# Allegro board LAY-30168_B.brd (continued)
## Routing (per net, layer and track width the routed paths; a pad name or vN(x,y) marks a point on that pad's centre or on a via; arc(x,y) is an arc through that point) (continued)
P3V3_SDA: length 106.9
  TOP w0.203: U44.1 144.91,88.9 C270.1
  TOP w0.279: 95.26,91.95 95.26,92.58 95.9,93.22 R418.2
  TOP w0.305: 95.26,91.95 U48.1 95.26,89.35 U49.1 v2(109.86,89.35) ; v2(111.51,95.38) 112.61,95.38 113.17,95.94 U46.1 113.98,96.46 R413.1 116.08,95.89 116.64,96.45 U45.3 ; U40.5 v2(143.2,83.44) 143.2,84.13 R378.1 ; U38.C5 v2(128.41,73.37) ; U38.D2 v2(129.21,70.97) U38.D1 v2(129.21,70.17) ; v2(125.09,80.51) R213.1 121.66,85.35 119.38,87.63 118.11,87.63 J34.1 116.33,86.74 115.32,85.72 114.43,85.72 114.43,86.11 v2(114.05,86.49) ; R388.2 138.18,74.55 v2(137.92,74.8) 137.92,77.22 138.94,78.23 ; U38.B2 v2(127.61,71.77) ; R215.1 127.25,66.17 126.11,67.31 126.11,68.33 ; v2(145.03,90.55) 145.03,91.44 144.65,91.82 142.62,91.82 R402.2 ; R394.1 146.42,89.16 v2(146.43,89.15) C270.1 145.54,86.74 v2(145.29,86.49) ; U38.F10 v2(130.81,78.17) ; U38.K5 v2(134.01,74.17) ; v2(122.17,76.07) R382.1 R381.1 R390.2
  TOP w0.381: v2(122.43,72.01) R383.1 123.07,72.76 R423.1 ; R381.1 v2(122.17,75.06)
  BOTTOM w0.127: 127.89,71.37 128.91,71.37
  BOTTOM w0.305: v2(134.01,74.17) 134.14,74.04 137.16,74.04 v2(137.92,74.8) ; 129.91,70.87 129.91,70.6 129.48,70.17 v2(129.21,70.17) ; 129.91,70.87 129.81,70.97 v2(129.21,70.97) ; 129.91,70.87 C265.1 ; v2(145.03,90.55) v2(146.43,89.15) ; 130.81,77.34 v2(130.81,78.17) ; C262.1 127.38,72 v2(127.61,71.77) ; v2(114.05,86.49) 112.72,86.49 v2(109.86,89.35) 109.86,93.73 v2(111.51,95.38) ; v2(128.41,73.37) 128.14,73.63 C266.1 ; v2(143.2,83.44) 143.2,84.39 v2(145.29,86.49)
  BOTTOM w0.381: v2(122.43,72.01) 122.43,74.8 v2(122.17,75.06)
  vias: v2(123.83,68.71) v2(124.84,68.71) v2(125.73,68.71) v2(139.06,80.26) v2(139.06,79.38) v2(139.95,80.26) v2(139.95,79.38) v2(139.95,78.36)
P5V0_SDA_USB_CONN_VBUS: length 17.9
  TOP w0.381: v2(144.78,71.12) 145.25,71.59 J41.1 ; L23.1 146.75,77.54 v2(146.43,77.22) 143.99,74.77 v2(141.25,74.77) ; v2(141.22,73.5) U39.4
  BOTTOM w0.381: v2(146.43,77.22) 144.4,75.18 144.4,73.66 144.78,73.28 v2(144.78,71.12) ; v2(141.25,74.77) 141.22,74.74 v2(141.22,73.5)
P5V_SDA: length 8.1
  TOP w0.254: U31.C1 U31.B1 U31.B2
  TOP w0.305: R212.1 125.48,63.12 125.98,62.61 130.81,62.61
  TOP w0.381: R379.1 v2(139.19,69.72)
  vias: v2(137.67,66.93) v2(138.56,66.93) v2(139.45,66.93) v2(139.7,75.69) v2(140.59,75.69) v2(141.48,75.69)
P5V_SDA_S:
  vias: v2(136.02,65.02) v2(136.02,64.14) v2(136.78,65.02) v2(136.78,64.14)
VDD_COIN_3V: length 5.7
  TOP w0.305: J6.2 88.48,39.37 D5.A 88.48,38.31 88,37.84 R16.1
VDD_HIGH_IN_3V3: length 59.9
  TOP w0.381: v2(83.19,31.11) 83.19,40.51 82.42,41.27 76.58,41.27 74.93,42.93 R14.1 75.82,44.96 76.33,44.45 J4.1 ; v2(65.41,29.21) 65.41,24.77 57.65,17.01 R311.2 R310.2
  BOTTOM w0.381: v2(65.41,29.21) 66.17,28.45 80.52,28.45 v2(83.19,31.11)
VDD_HIGH_IN_MCU: length 20.6
  TOP w0.203: U1.P12 61.35,50.82 61.73,50.43 62.5,50.43 63.02,49.91 63.37,49.91
  TOP w0.305: J4.2 76.48,46.99 75.97,46.48 R14.2 74.12,46.48 v2(73.79,46.82) ; 63.37,49.91 65.15,49.91 65.33,49.73 66.37,49.73 67.43,50.79 C15.1 v2(68.45,50.79)
  BOTTOM w0.305: v2(68.45,50.79) C16.1 72.14,50.79 73.79,49.15 v2(73.79,46.82)
VDD_SNVS_3V3: length 78.5
  TOP w0.305: v2(81.92,20.95) 81.92,31.53 D4.A ; U5.4 C59.1 42.8,21.21 44.32,19.68 44.32,18.29 47.24,15.37 47.24,9.4 48.18,8.46 58.88,8.46 v2(59.44,9.02) 59.69,9.27 59.69,14.1 R354.2 58.68,14.23 58.55,14.1
  TOP w0.381: 58.55,14.1 R34.2
  BOTTOM w0.305: v2(81.92,20.95) 78.36,17.4 78.36,15.49 71.58,8.71 59.74,8.71 v2(59.44,9.02)
VDD_SNVS_IN: length 31.8
  TOP w0.102: 59.23,50.24 59.05,50.42 59.05,51.98 U1.M9
  TOP w0.254: v2(59.39,47.45) 59.27,47.56 59.27,50.2 59.23,50.24
  TOP w0.305: v2(67.69,40.13) 73.66,40.13 75.32,38.47 C23.1 77.97,38.47 78.36,38.86 R15.2 80.77,38.86 J5.2
  BOTTOM w0.305: v2(67.69,40.13) 65.48,40.13 59.81,45.8 R21.1 59.81,47.02 v2(59.39,47.45)
VDD_SOC_IN: length 23.5
  TOP w0.254: U1.H9 v1(59.07,54.59) U1.J9 v1(59.72,54.6) U1.H9 ; U1.H9 59.72,55.24 U1.G9 59.54,55.72 59.54,56.07 U1.F9 59.39,56.22 v1(59.07,56.54) U1.F8 U1.F7 v1(57.77,56.54) U1.F6 v1(57.12,55.89) U1.G6 v1(57.12,55.24) U1.H6 ; U1.J5 v1(56.47,53.95)
  INT1 w0.102: 58.09,52.32 58.09,51.24 ; 58.09,52.32 58.09,52.97 ; 58.09,52.32 58.1,52.32 60.04,52.32 60.04,52.32 ; v1(56.47,53.95) 56.49,53.95 56.79,54.25 56.79,54.92 v1(57.12,55.24) ; 58.09,52.97 60.04,52.97 60.04,52.98 ; 58.09,52.97 58.09,53.63 ; 60.04,53.66 60.01,53.62 58.1,53.62 58.09,53.63 ; 60.04,53.66 60.04,52.98 ; 60.04,53.66 60.04,54.25 ; 60.04,52.98 60.04,52.32 ; 60.04,52.32 60.04,51.62 ; 58.09,54.26 58.09,54.92 ; 58.09,54.26 58.1,54.27 58.76,54.27 ; 58.09,54.26 58.09,53.63
  BOTTOM w0.305: C11.1 58.11,56.89 v1(57.77,56.54)
  vias: v2(49.53,44.07) v2(49.91,44.7) v2(49.91,43.56)
VDD_USB_3V: length 7.5
  TOP w0.254: v1(58.42,53.94) 58.74,53.62 U1.K8
  BOTTOM w0.127: 59.13,53.34 58.85,53.34 58.42,53.77 v1(58.42,53.94)
  BOTTOM w0.152: 59.13,53.34 59.31,53.16 59.31,51.31 59.56,51.05
  BOTTOM w0.305: 59.56,51.05 59.82,50.8 C83.1 61.62,48.49 C82.1
VDDA_ADC_3P3_MCU: length 23.9
  TOP w0.203: U1.N14 62.73,51.59 69.01,51.59 69.22,51.38 C7.1
  TOP w0.305: C7.1 C6.1 71.38,50.79 73.77,48.41 78.34,48.41 80.26,46.48 R12.2 82.42,46.48 82.93,46.99 J3.2
VDDA_ADC_3V3: length 5.2
  TOP w0.305: R12.1 C57.1 81.02,43.55 R44.2
  TOP w0.381: R12.1 82.3,44.96 82.8,44.45 J3.1
AUD_INT: length 111.2
  TOP w0.127: R96.1 v2(121.41,21.6) 120.41,21.6 119.63,20.83 101.85,20.83 100.08,22.61 100.08,31.75 94.11,37.72 94.11,44.45 92.46,46.1 v2(92.46,46.61) ; U1.H13 62.17,54.92 62.51,54.59 63.14,54.59 63.58,54.15 75.18,54.15 77.17,52.16 79.61,52.16 80.16,52.7 88.81,52.7 89.57,53.47 R287.2 v2(90.05,52.71) ; R222.2 v2(133.99,14.99) R275.1
  BOTTOM w0.127: v2(133.99,14.99) 133.05,14.99 132.16,15.88 129.92,15.88 129.71,15.66 123.32,15.66 121.92,17.06 121.92,18.16 122.53,18.77 122.53,21.11 122.03,21.6 v2(121.41,21.6) ; v2(90.05,52.71) 92.46,50.3 v2(92.46,46.61)
BACKLIGHT_CTL: length 90
  TOP w0.127: U8.4 v2(94.36,67.63) 93.54,68.45 R314.1 ; v2(96.14,31.11) 90.3,31.11 86.36,27.18 R344.1 ; U1.B14 63.53,58.82 64.85,60.15 84.4,60.15 v2(85.85,61.59) 86.33,62.08 87.48,62.08 87.83,61.72 87.83,61.16 87.5,60.83 87.5,58.8 v2(87.88,58.42)
  BOTTOM w0.127: v2(94.36,67.63) 94.04,67.63 92.2,65.79 92.2,64.52 89.92,62.23 86.49,62.23 v2(85.85,61.59) ; v2(96.14,31.11) 98.17,33.15 98.17,48.73 89.12,57.78 88.14,57.78 87.88,58.04 v2(87.88,58.42)
BL+: length 5.6
  TOP w0.254: R63.2 v2(91.57,67.56)
  BOTTOM w0.254: J8.A2 94.15,69.55 94.23,69.47 94.23,68.96 92.84,67.56 v2(91.57,67.56)
BL-:
  vias: v2(96.27,70.99) v2(96.27,70.1)
BOOT0_LED: length 4.4
  TOP w0.127: U38.K2 135.63,71.37 R392.1 R388.1
BOOT1: length 3.3
  TOP w0.127: U38.K1 135.85,70.57 R389.1
BOOT2: length 5.1
  TOP w0.127: U38.C6 128.41,74.17 124.08,74.17 R390.1
BOOT3: length 4.8
  TOP w0.127: U38.B10 126.28,79.5 R391.1
BOOT_FLASH: length 5.8
  TOP w0.127: J42.2 128.81,79.6 U38.C10
CAN1_H: length 16
  TOP w0.107: R87.2 FL1.1 65.18,12.46 65.48,12.16 R88.1 65.48,9.4 C101.2 65.48,9.4 D11.2 66.2,8.01 66.3,7.9 66.3,7.23 66.11,7.04 63.99,7.04 63.49,6.54 63.49,5.08 61.82,3.4 J11.1
CAN1_L: length 16.3
  TOP w0.107: J11.3 65.43,3.4 63.75,5.08 63.75,6.43 64.1,6.78 64.69,6.78 64.8,6.67 64.8,6.51 64.9,6.4 65.12,6.4 65.22,6.51 65.22,6.67 65.33,6.78 66.21,6.78 66.56,7.13 66.56,7.9 66.67,8.01 D11.1 67.38,9.4 C103.1 67.38,9.4 R89.2 67.38,12.16 67.68,12.46 FL1.2 R91.2
CAN2_RX: length 45.3
  TOP w0.127: v2(71.75,35.43) 72.78,34.4 U12.4 ; U1.L10 v1(60.37,52.65)
  BOTTOM w0.102: 64.14,50.16 62.69,50.16 61.18,51.67 60.89,51.67 60.7,51.86 60.7,52.15 60.37,52.48 v1(60.37,52.65)
  BOTTOM w0.127: v2(71.75,35.43) 74.3,37.97 74.3,49.4 72.26,51.44 68.33,51.44 67.06,50.16 64.14,50.16
CAN2_TX: length 49.6
  TOP w0.127: U1.H14 63.68,54.92 63.83,55.07 66.68,55.07 66.9,55.28 72.22,55.28 72.57,54.94 75.06,54.94 v2(77.42,52.58) ; U12.1 76.59,31.48 v2(72.64,35.43)
  BOTTOM w0.127: v2(77.42,52.58) 74.8,49.96 74.8,37.59 v2(72.64,35.43)
CAN_STBY: length 156
  TOP w0.127: SW7.3 87.98,82.07 R260.2 88.78,81.78 89.03,81.53 89.03,80.77 89.41,80.39 104.31,80.39 106.17,78.53 106.17,73.91 106.97,73.11 106.97,57.84 103.83,54.7 87.46,54.7 86.36,53.59 79.79,53.59 v2(79.63,53.44) 79.14,52.95 78.4,52.95 75.52,55.83 72.95,55.83 72.72,56.06 66.4,56.06 66.17,55.83 63.7,55.83 63.44,55.57 U1.G14 ; v2(60.2,37.34) 62.48,37.34 65.02,34.8 66.04,34.8 68.58,32.26 v2(68.58,31.75) 72.01,28.32 72.01,20.95 72.9,20.07 75.32,20.07 v2(76.59,18.8)
  BOTTOM w0.127: v2(60.2,37.34) 59.94,37.34 58.67,38.61 58.67,40.26 57.15,41.78 R169.1 ; v2(68.58,31.75) 73.01,31.75 78.99,37.73 78.99,49.91 78.61,50.29 78.61,51.69 79.63,52.7 v2(79.63,53.44) ; R92.1 v2(76.59,18.8)
CAN_VIO_3V3: length 6
  TOP w0.305: U12.5 v2(72.78,16)
  BOTTOM w0.305: C100.1 v2(72.78,16) R86.1 73.67,16.77 74.42,17.52 R90.1
CSI_1V8: length 3.6
  TOP w0.305: v2(133.35,5.84) 133.96,6.46 J35.15
  BOTTOM w0.305: L20.2 133.35,5.21 v2(133.35,5.84)
  BOTTOM w0.381: C247.1 v2(133.35,5.84)
CSI_D2: length 20.1
  TOP w0.127: v2(124.08,16.26) 124.59,15.75 124.59,12.45 127,10.03 127.76,10.03 129.47,8.33 J35.6
  BOTTOM w0.127: R229.1 123.3,24.14 124.08,23.37 v2(124.08,16.26)
CSI_D3: length 19
  TOP w0.127: J35.4 128.47,8.19 127.38,9.27 126.62,9.27 123.32,12.57 v2(123.32,17.14)
  BOTTOM w0.127: R228.1 123.44,23.11 123.7,22.86 123.7,17.53 v2(123.32,17.14)
CSI_D4: length 17.6
  TOP w0.127: J35.3 127.96,8.18 127.38,8.76 126.62,8.76 122.43,12.95 v2(122.43,17.14)
  BOTTOM w0.127: v2(122.43,17.14) 122.93,17.65 R227.1
CSI_D5: length 17.1
  TOP w0.127: J35.5 128.96,8.2 127.51,9.65 126.75,9.65 124.08,12.32 v2(124.08,15.24)
  BOTTOM w0.127: R226.1 122.04,19.17 121.54,18.67 121.54,16.9 123.2,15.24 v2(124.08,15.24)
CSI_D6: length 4.4
  TOP w0.127: J35.7 129.96,8.34 128.4,9.91 128.4,10.41 128.26,10.55 R225.1
CSI_D7: length 3.4
  TOP w0.127: R224.1 130.18,9.78 130.96,8.99 J35.9
CSI_D8: length 27.2
  TOP w0.127: v2(131.44,14.99) 131.44,10.55 131.96,10.03 J35.11
  BOTTOM w0.127: v2(131.44,14.99) 130.94,15.49 130.3,15.49 129.57,14.76 123.25,14.76 119.89,18.12 119.89,20.19 119.76,20.32 R223.1
CSI_D9: length 3.6
  TOP w0.127: R222.1 132.87,9.43 132.87,8.61 132.96,8.52 J35.13
CSI_HSYNC: length 3.5
  TOP w0.127: J35.16 134.47,9.88 135.13,10.55 R221.1
CSI_MCLK: length 3.2
  TOP w0.127: J35.12 132.47,10.3 R218.1
CSI_PIXCLK: length 3.8
  TOP w0.127: J35.8 130.47,8.47 128.91,10.03 R217.1
CSI_PWDN: length 252.2
  TOP w0.127: D17.C v2(137.53,15.24) ; v2(85.47,50.8) 84.96,50.29 84.96,49.63 85.44,49.15 86.36,49.15 87,49.78 v2(91.82,49.78) 103.12,49.78 108.58,55.24 v2(113.67,55.24) 118.24,50.67 118.24,46.86 J38.2 ; U1.L11 v1(61.02,52.65)
  BOTTOM w0.102: 64.82,52.12 61.71,52.12 61.19,52.65 v1(61.02,52.65)
  BOTTOM w0.127: v2(85.47,50.8) 82.8,53.47 81.56,53.47 80.19,54.84 76.3,54.84 74.24,52.78 67.39,52.78 66.73,52.12 64.82,52.12 ; v2(113.67,55.24) 113.67,61.34 87.47,87.53 59.6,87.53 54.37,82.3 34.14,82.3 J22.7 ; v2(91.82,49.78) 91.82,43.4 92.43,42.8 93.34,42.8 95.63,40.51 95.63,35.81 94.61,34.8 94.61,26.92 97.28,24.26 117.86,24.26 118.92,23.19 118.92,18.66 123.13,14.45 136.74,14.45 v2(137.53,15.24)
CSI_VSYNC: length 4.4
  TOP w0.127: J35.18 135.47,8.72 135.76,9.02 136.14,9.02 137.67,10.55 R220.1
DC_5V_IN: length 6.2
  BOTTOM w0.381: v2(14.99,14.22) 16.76,14.22 17.4,14.86 R6.1
DCDC_3V3: length 175.4
  TOP w0.203: C268.1 144.4,87.12 143.66,87.86 U44.8
  TOP w0.254: U1.J10 v1(60.37,53.95) ; C252.1 28.52,36.76 U37.A1 ; U1.F5 v1(57.12,56.54) U1.E6 v1(57.12,57.19) ; U1.E9 U1.F10 v1(60.37,56.54)
  TOP w0.305: U48.8 95.26,95.62 C277.1 ; R57.1 v2(74.93,50.8) ; v2(143.38,85.6) 143.38,86.11 143.89,86.61 C268.1 ; R324.1 93.34,70.99 v2(94.11,71.75) ; v2(55.75,82.29) R284.1 v2(57.28,82.29) ; R179.1 v2(45.47,86.62) ; R293.1 v2(68.95,39.36) ; R245.1 v2(87.98,93.09) ; U46.6 113.17,93.08 C276.1 v2(114.43,92.71) ; R244.1 v2(86.71,93.09) ; v2(118.24,91.95) R411.1 117.47,91.19 C275.1 117.29,91.37 U45.7 ; C220.1 v2(87.38,65.28) ; v2(82.3,51.05) C198.1 ; J35.14 133.47,8.82 v2(133.39,8.9) ; R246.1 v2(89.25,93.09) ; R419.2 v2(110.62,93.22) ; R412.1 129.79,87.88 v2(130.05,87.63) ; R243.1 v2(85.44,93.09) ; R236.1 v2(70.2,93.09) ; R354.1 v2(59.56,16) ; R27.1 v2(27.81,43.18) ; v2(140.34,14.61) 140.21,14.48 R232.1 ; R239.1 v2(77.18,93.09) ; R238.1 v2(72.74,93.09) ; R422.2 v2(92.71,87.12) ; v2(83.06,19.43) 85.72,16.76 R332.1 R349.1 ; R241.1 v2(79.72,93.09) ; D12.A v2(29.84,84.84) ; C199.1 89.03,47.62 v2(88.01,48.64) ; R242.1 v2(80.99,93.09) ; R234.1 v2(138.69,14.47) ; R393.1 v2(125.47,90.94) ; R235.1 v2(68.93,93.09) ; R237.1 v2(71.47,93.09) ; R240.1 v2(78.45,93.09)
  TOP w0.381: R44.1 80.14,42.29 v2(80.39,42.04) ; R219.1 136.4,11.3 v2(137.03,11.94) ; R316.1 v2(97.54,41.66) ; R177.1 v2(39.64,85.85) ; C278.1 95.5,86.01 v2(95.26,86.25) U49.6 ; C252.1 v2(28.84,35.69) ; v2(118.87,24) 119.25,23.62 C196.1 ; C209.1 v2(33.27,88.01) ; C206.1 v2(113.41,83.06) ; R311.1 v2(56.13,16.13) ; R350.1 v2(89.41,27.18) ; R176.1 v2(37.1,85.85) ; v2(24.13,58.93) 24.77,59.56 v2(24.77,67.31) ; C216.1 v2(79.63,77.09) ; C277.1 v2(93.6,96.39) ; C207.1 v2(40.89,88.01) ; R401.1 v2(143.38,85.6) ; v2(128.4,12.06) 128.4,12.7 C203.1 ; R178.1 v2(42.18,85.85) ; R174.1 v2(24.4,85.85) ; C212.1 v2(80.77,55.37) ; C208.1 v2(102.87,78.74) ; C200.1 v2(91.57,24) ; C204.1 v2(132.33,14.99) ; R346.1 v2(87.38,27.18)
  INT1 w0.102: v1(57.12,57.19) 57.3,57.19 57.62,57.52 58.29,57.52 ; v1(57.12,57.19) v1(57.12,56.54) 57.31,56.54 57.63,56.87 58.01,56.87 58.29,57.15 ; v1(57.12,57.19) 57.12,57.37 57.44,57.7 57.44,57.98 57.64,58.17 58.29,58.17 ; 60.69,52.97 60.69,53.62 ; 60.69,52.97 60.69,52.32 ; 60.69,52.97 62,52.97 ; 60.69,53.62 v1(60.37,53.95) 60.69,54.27 ; 60.69,53.62 62,53.62 ; 61.35,51.74 61.35,57.52 ; 61.35,57.52 60.21,57.52 ; 61.35,57.52 61.35,58.97 ; 60.04,58.17 60.04,58.82 61.43,58.82 ; 60.04,58.17 59.1,58.17 ; 60.04,58.17 61.43,58.17 ; 60.04,58.17 60.04,57.63 ; 62,54.92 60.71,54.92 60.69,54.93 ; 60.69,54.27 60.69,54.93 ; 60.69,54.27 62,54.27 ; 60.69,54.93 60.69,56.52 ; 62,56.22 60.75,56.22 ; 59.39,58.82 59.39,57.57 ; 60.69,52.32 60.69,51.63 ; 60.69,52.32 62,52.32 ; 60.69,59.04 60.69,56.91
  BOTTOM w0.254: C72.1 59.92,56.99 v1(60.37,56.54) ; v2(64.9,54.61) R55.1
  BOTTOM w0.305: C221.1 80.01,64.95 v2(80.52,65.46) ; R325.1 83.94,73.54 v2(83.82,73.66)
  BOTTOM w0.381: v2(105.41,51.31) 105.97,50.75 C211.1 ; C219.1 v2(86.26,59.18) ; C210.1 108.84,52.7 v2(108.84,52.96) ; v2(111,43.05) C193.1 ; C201.1 v2(77.09,27.69) ; C202.1 v2(131.95,12.06) ; L19.2 136.77,7.89 R230.1 C249.1 137.36,10.03 v2(137.62,9.78) ; v2(143.38,85.6) 141.99,84.2 133.48,84.2 v2(130.05,87.63) 126.74,90.94 v2(125.47,90.94) 124.46,91.95 v2(118.24,91.95) ; C217.1 100.46,59.31 v2(99.57,58.42) ; C222.1 v2(10.54,55.37) ; C195.1 v2(118.36,19.68) ; v2(137.03,11.94) 136.65,12.32 136.14,12.32 ; C215.1 v2(87.38,81.79) ; C246.1 133.35,8.86 v2(133.39,8.9) ; C214.1 v2(70.1,79.76) ; v2(71.75,17.52) R86.2 ; C213.1 77.09,83.44 76.71,83.06 v2(76.33,83.06) ; v2(120.52,20.45) 120.4,20.57 C194.1 ; C218.1 v2(68.71,66.55) ; R130.1 v2(112.64,41.82) ; R372.1 22.1,56.9 v2(24.13,58.93) ; C197.1 v2(91.49,53.47)
  vias: v2(27.56,67.94) v2(28.57,67.94) v2(33.15,41.88) v2(33.91,41.88) v2(34.67,41.88) v2(46.23,28.43) v2(47.73,28.43) v2(51.44,18.03) v2(51.44,17.02) v2(52.58,17.02) v2(53.59,18.03) v2(53.59,17.02) v2(56.9,64.64) v2(56.9,63.88) v2(69.22,54.81) v2(70.48,54.81) v2(71.75,54.81) v2(83.82,74.55) v2(84.58,74.55) v2(84.58,73.66) v2(121.67,30.86) v2(121.67,30.23)
DCDC_3V3_PG: length 22
  TOP w0.254: U6.3 35.38,37.04 32.89,34.54 32.89,23.36 TP8.1 C55.1 C56.1 34.03,18.19 33.85,18.01 U3.1
ENET_3V3: length 29.3
  TOP w0.305: v2(111.39,48.89) 110.75,48.89 110.45,48.58 U16.17
  TOP w0.381: J19.12 v2(102.61,31.75) ; R144.2 v2(102.49,45.5) ; R129.1 v2(103.38,40.29) 103.38,41.54 R322.2 ; v2(114.94,44.74) R132.1 R134.2 ; R147.2 108.2,53.59 108.71,54.1 110.12,54.1 110.74,53.48 v2(110.74,52.99) R145.2 R151.2 ; v2(114.94,30.12) C148.1 J19.1 ; R139.2 v2(114.8,50.2) ; R131.1 v2(114.94,43.59) ; 114.43,47.91 v2(115.19,47.91) ; R126.1 v2(115.06,40.29)
  BOTTOM w0.305: 102.24,48.43 v2(102.23,48.42)
  BOTTOM w0.381: R309.1 102.24,48.43
  vias: v2(102.99,48.41) v2(109.22,41.05) v2(109.22,39.4)
ENET_B-CAST-OFF: length 6.2
  TOP w0.127: U16.19 R151.1 108.97,51.22 108.84,51.35 108.84,52.2 TP12.1
ENET_CONFIG0: length 3.8
  TOP w0.254: U16.28 105.64,45.75 105.22,46.16 105.22,46.29 104.87,46.64
  TOP w0.381: R142.1 R140.1 104.87,46.64
ENET_CONFIG1: length 4.1
  TOP w0.127: U16.29 105.28,45.25 v2(105.16,45.37) 105.03,45.5 R144.1
  BOTTOM w0.127: v2(105.16,45.37) 104.39,44.61 R143.1
ENET_CRS_DV: length 61.9
  TOP w0.127: U1.C12 v1(61.67,58.49) ; U16.18 109.95,48.99 110.58,49.62 110.58,50 v2(111.12,50.55) 110.74,50.93 R145.1 R141.1
  BOTTOM w0.127: v2(111.12,50.55) 111.12,51.69 109.86,52.96 109.86,54.48 103.21,61.13 85.73,61.13 85.31,60.71 65.66,60.71 63.45,58.49 v1(61.67,58.49)
ENET_INT: length 200.8
  TOP w0.127: U1.G13 62.32,55.24 63.47,55.24 63.68,55.45 66.52,55.45 66.74,55.66 72.48,55.66 72.72,55.42 75.39,55.42 78.24,52.57 79.48,52.57 80.12,53.21 88.78,53.21 89.54,53.98 v2(97.79,53.98) 104.08,53.98 107.67,57.57 107.67,78.23 104.43,81.47 95.57,81.47 v2(92.08,84.96) 91.82,85.22 83.69,85.22 82.42,83.95 R428.2 75.69,80.64 73.53,78.48 R262.2 68.08,78.48 67.94,78.61 R263.2 67.56,79.25 63.88,82.93 54.34,82.93 49.52,78.11 37.47,78.11 J22.6 30.73,84.85 30.73,94.02 J21.13 ; R152.1 106.17,50.62 107.01,49.78 107.56,49.78 v2(108.45,48.9) U16.21 ; v2(91.31,87.63) J50.2
  BOTTOM w0.127: v2(108.45,48.9) 107.56,48.01 105.25,48.01 103.86,49.4 R309.2 102.99,50.27 99.28,53.98 v2(97.79,53.98) ; v2(92.08,84.96) 91.31,85.72 v2(91.31,87.63)
ENET_LED0/NWAYEN: length 35.9
  TOP w0.127: U16.30 105.29,44.75 v2(105.16,44.61) 105.03,44.48 R148.1 ; J19.2 v2(113.99,28.86)
  BOTTOM w0.127: v2(105.16,44.61) 101.22,40.67 101.22,30.1 103.25,28.07 113.2,28.07 v2(113.99,28.86)
ENET_LED1/SPEED: length 24.2
  TOP w0.127: U16.31 105.68,44.25 v2(105.16,43.72) 104.9,43.47 R149.1 ; J19.11 v2(104.45,28.86)
  BOTTOM w0.127: v2(104.45,28.86) 103.22,28.86 101.73,30.35 101.73,40.29 v2(105.16,43.72)
ENET_MDC: length 85.9
  TOP w0.127: U16.12 v2(112.52,45.25) 113.03,44.74 R132.2 ; U1.A7 58.09,61.52 62.1,65.53 64.26,65.53 66.55,67.82 72.9,67.82 76.33,71.25 86.87,71.25 87.38,70.74 89.63,70.74 92.3,73.41 100.66,73.41 103.28,70.79 103.28,60.1 v2(103,59.82)
  BOTTOM w0.127: v2(112.52,45.25) 112.52,46.45 109.07,49.9 109.07,50.82 107.73,52.16 107.73,55.08 v2(103,59.82)
ENET_MDIO: length 89.2
  TOP w0.127: v2(101.6,58.42) 102.49,59.31 102.49,60.07 102.87,60.45 102.87,70.66 100.51,73.03 92.46,73.03 89.79,70.36 87,70.36 86.54,70.82 76.66,70.82 73.28,67.44 67.56,67.44 66.8,66.67 v2(66.8,65.79) ; U1.C7 v1(57.77,58.49) ; R131.2 113.54,43.94 113.28,44.2 112.78,44.2 v2(112.52,44.45) 112.22,44.75 U16.11
  BOTTOM w0.102: v1(57.77,58.49) 57.77,60.58
  BOTTOM w0.127: v2(101.6,58.42) 106.43,53.59 106.43,52.83 108.67,50.58 108.67,49.8 112.05,46.42 112.05,44.92 v2(112.52,44.45) ; v2(66.8,65.79) 62.66,65.79 57.77,60.89 57.77,60.58
ENET_PHYAD0: length 3.5
  TOP w0.127: U16.13 112.39,45.75 112.52,45.88 R134.1 R137.1
ENET_PHYAD1: length 4.5
  TOP w0.127: U16.14 112,46.25
  TOP w0.254: R135.1 R138.1 113.03,47.91 112.78,47.66 112.78,47.02 112,46.25
ENET_RST: length 198
  TOP w0.127: R323.1 102.36,41.67 D18.C 99.96,42.55 v2(95.89,42.55) ; v2(100.84,79.25) 104.18,79.25 105.28,78.15 105.28,58.18 103.13,56.02 85.59,56.02 85.09,56.52 85.09,57.02 v2(84.84,57.28) 84.72,57.39 66.54,57.39 65.66,56.52 63.5,56.52 63.21,56.22 62.65,56.22 U1.F14 ; v2(98.93,82.04) 95.63,82.04 v2(91.95,85.72) 56.42,85.72 49.31,78.61 39.51,78.61 J22.5 37.52,84.51 38.61,85.6 38.61,86.74 39.24,87.37 R177.2 39.64,88.01 40.91,89.28 40.91,94.01 J21.5 ; J49.2 98.3,92.08 v2(98.3,90.93)
  BOTTOM w0.127: v2(84.84,57.28) 85.85,57.28 86.36,56.77 88.98,56.77 94.23,51.52 94.23,44.2 v2(95.89,42.55) ; v2(98.3,90.93) 97.54,90.17 96.39,90.17 v2(91.95,85.72) ; v2(98.93,82.04) 100.84,80.14 v2(100.84,79.25)
ENET_RXD0: length 64.1
  TOP w0.127: U1.E12 v1(61.67,57.19) ; U16.16 111.76,47.25 111.89,47.38 111.89,49.05 111.58,49.36 111.3,49.36 111.12,49.53 v2(111.12,49.66) 111.12,49.88 111.41,50.16 112.27,50.16 112.9,50.8 R150.1
  BOTTOM w0.127: v2(111.12,49.66) 110.62,50.16 110.62,51.77 109.35,53.04 109.35,54.34 102.87,60.82 85.97,60.82 85.47,60.33 65.91,60.33 63.12,57.53 62.01,57.53 v1(61.67,57.19)
ENET_RXD1: length 67
  TOP w0.127: v2(87.3,61.59) 86.53,60.83 85.85,60.83 84.86,59.84 65,59.84 63.66,58.5 62.53,58.5 62.31,58.29 62.31,58.04 62.13,57.85 61.68,57.85 U1.D12 ; U16.15 111.87,46.75 112.19,47.07 112.19,48.47 v2(112.52,48.8) 112.52,49.53 113.19,50.2 R139.1
  BOTTOM w0.127: v2(87.3,61.59) 104.01,61.59 112.27,53.34 112.27,52.58 113.42,51.44 R136.1 v2(112.52,48.8)
ENET_RXER: length 58.9
  TOP w0.127: U1.C13 62,58.37 62.33,58.7 62.33,58.95 62.51,59.14 63.39,59.14 64.85,60.59 84.09,60.59 85.88,62.38 87.6,62.38 88.14,61.85 88.14,60.45 v2(88.01,60.33) ; U16.20 108.95,49.58 v2(108.2,50.32) R147.1 R146.1
  BOTTOM w0.127: v2(88.01,60.33) 96.65,60.33 104.39,52.58 105.95,52.58 v2(108.2,50.32)
ENET_RXM: length 25.3
  TOP w0.107: J19.8 107.69,27.95 107.8,28.06 107.96,28.06 108.07,28.16 108.07,28.51 107.96,28.61 107.8,28.61 107.7,28.72 107.7,28.93 107.8,29.04 107.96,29.04 108.07,29.15 108.07,29.36 107.96,29.47 107.8,29.47 107.7,29.57 107.7,29.79 107.8,29.89 107.96,29.89 108.07,30 108.07,30.21 107.96,30.32 107.8,30.32 107.7,30.43 107.7,30.64 107.8,30.75 107.96,30.75 108.07,30.85 108.07,32.27 109.09,33.29 109.09,33.96 108.9,34.14 U17.3 107.18,34.14 106.65,34.67 106.65,34.85 106.55,34.95 106.04,34.95 105.66,35.34 105.66,37.35 106.3,37.99 106.3,39.04 106.19,39.15 C147.1 R129.2 106.29,40.79 106.29,41.16 106.7,41.57 108.34,41.57 108.57,41.8 108.57,42.35 108.45,42.47 U16.4
ENET_RXP: length 25.4
  TOP w0.107: U16.5 108.95,42.47 108.83,42.35 108.83,41.69 108.45,41.31 106.81,41.31 106.55,41.05 106.55,40.8 R128.2 C146.1 106.66,39.15 106.56,39.04 106.56,37.88 105.92,37.24 105.92,35.45 106.15,35.21 106.53,35.21 106.65,35.34 106.65,35.5 107.18,36.02 U17.1 108.92,36.02 109.09,35.85 109.09,34.32 109.35,34.07 109.35,33.18 108.33,32.16 108.33,28.16 108.44,28.06 108.6,28.06 108.71,27.95 J19.7
ENET_TX_CLK: length 67
  TOP w0.127: U1.B13 62,59.02 62.31,59.34 62.31,59.62 62.89,60.2 63.88,60.2 64.66,60.97 83.2,60.97 TP25.1 84.99,62.76 87.99,62.76 88.52,62.23 88.52,60.07 88.14,59.69 v2(88.14,59.44) ; v2(112.52,43.31) 112.05,43.31 111.61,43.75 U16.9
  BOTTOM w0.127: v2(88.14,59.44) 88.39,59.18 88.39,58.8 89.03,58.17 90.42,58.17 91.06,58.8 95,58.8 105.41,48.39 107.19,48.39 108.12,49.31 108.62,49.31 111.67,46.27 111.67,44.58 112.52,43.73 v2(112.52,43.31)
ENET_TXD0: length 56.8
  TOP w0.127: U1.B12 61.66,59.14 61.66,59.77 63.63,61.73 81.42,61.73 TP26.1 83.19,63.5 88.39,63.5 89.53,62.36 v2(89.53,59.44) ; U16.24 106.95,48.75 106.05,49.66 106.05,49.91 105.28,50.67 v2(104.78,50.67)
  BOTTOM w0.127: v2(89.53,59.44) 89.66,59.56 95.89,59.56 v2(104.78,50.67)
ENET_TXD1: length 56.8
  TOP w0.127: v2(105.16,49.28) 105.16,47.62 105.53,47.25 U16.25 ; v2(90.42,59.05) 90.04,59.44 90.04,62.48 88.64,63.89 82.3,63.89 80.54,62.12 63.52,62.12 61.35,59.95 U1.A12
  BOTTOM w0.127: v2(105.16,49.28) 95.25,59.18 90.55,59.18 v2(90.42,59.05)
ENET_TXEN: length 56.5
  TOP w0.127: v2(107.31,49.28) 107.45,49.14 U16.23 ; U1.A13 62,59.71 62.87,60.58 63.63,60.58 64.4,61.35 82.41,61.35 84.2,63.14 88.24,63.14 88.9,62.48 v2(88.9,59.82)
  BOTTOM w0.127: v2(107.31,49.28) 106.59,50 106.59,51.27 105.79,52.07 104.27,52.07 96.39,59.94 89.03,59.94 v2(88.9,59.82)
ENET_TXM: length 25.9
  TOP w0.107: J19.4 111.77,27.95 111.88,28.06 112.04,28.06 112.15,28.16 112.15,34.83 112.03,34.95 111.63,34.95 111.51,34.83 111.51,34.43 111.22,34.14 U17.4 110.03,34.14 109.6,34.58 109.6,35.89 109.47,36.02 109.47,36.86 110.33,37.72 111.74,37.72 111.88,37.86 111.88,38.91 111.78,39.02 111.38,39.02 R127.2 111.88,40.79 111.88,41.05 111.63,41.3 110,41.3 109.57,41.73 109.57,42.35 109.45,42.47 U16.6
ENET_TXP: length 25.9
  TOP w0.107: U16.7 109.95,42.47 109.83,42.35 109.83,41.84 110.11,41.56 111.73,41.56 112.14,41.16 112.14,40.8 R126.2 C144.1 112.25,39.02 112.14,38.91 112.14,37.75 111.85,37.46 110.44,37.46 109.73,36.75 109.73,36.13 109.83,36.02 U17.6 111.33,36.02 111.51,35.85 111.51,35.32 111.61,35.21 112.14,35.21 112.41,34.94 112.41,31.81 112.52,31.71 112.59,31.71 112.7,31.6 112.7,31.39 112.59,31.28 112.52,31.28 112.41,31.17 112.41,30.96 112.52,30.85 112.59,30.85 112.7,30.75 112.7,30.53 112.59,30.43 112.52,30.43 112.41,30.32 112.41,30.11 112.52,30 112.59,30 112.7,29.89 112.7,29.68 112.59,29.57 112.52,29.57 112.41,29.47 112.41,29.25 112.52,29.15 112.59,29.15 112.7,29.04 112.7,28.83 112.59,28.72 112.52,28.72 112.41,28.61 112.41,28.16 112.52,28.06 112.68,28.06 112.79,27.95 J19.3
FLASH_VCC: length 69.1
  TOP w0.254: U19.D1 52.71,38.73 52.07,38.73 ; U19.B4 55.33,41.17 v1(55.25,41.17) ; v2(55.37,44.45) 55.37,43.89 56.85,42.42 v1(57.15,42.42) ; U19.E4 v2(56.24,37.26) ; U1.K5 v1(56.47,53.3)
  TOP w0.305: v2(54.23,45.11) 54.89,44.45 v2(55.37,44.45) ; v2(51.82,38.99) 52.07,38.73
  TOP w0.381: v2(51.82,37.08) 52.45,36.45 55.42,36.45 v2(56.24,37.26) ; v2(57.66,34.04) v2(60.83,34.04)
  BOTTOM w0.102: v1(56.47,53.3) 56.14,52.97 56.14,52.42 55.88,52.15 55.88,52.14 55.83,52.09
  BOTTOM w0.254: R171.1 54.08,44.96 v2(54.23,45.11) 54.23,46.1 54.41,46.28 54.41,49.58 54.73,49.9 C80.1 55.17,50.08 55.54,50.08 56.11,50.65 C81.1 56.11,51.1 55.83,51.38 55.83,52.09 ; v1(55.25,41.17) 55.25,42.03 55.02,42.27 55.02,43.55 55.27,43.81 R168.1 55.58,44.25 v2(55.37,44.45)
  BOTTOM w0.305: v2(51.82,38.99) 51.43,39.38 R294.1 ; R170.1 55.51,44.58 v2(55.37,44.45) ; C163.1 55.6,41.18 v1(55.25,41.17) ; R360.1 v2(56.39,24.14)
  BOTTOM w0.33: v2(60.83,34.04) 60.83,37.59 60.07,38.35 59.69,38.35 59.18,38.86 59.18,40.77 57.53,42.42 v1(57.15,42.42)
  BOTTOM w0.381: v2(56.41,20.19) 61.34,25.13 61.34,26.54 ; R358.1 59.31,26.54 61.34,26.54 ; 61.34,26.54 61.72,26.92 R359.1 61.72,29.08 60.83,29.97 v2(60.83,34.04) ; v2(56.24,37.26) 56.22,37.25 C162.1 56.22,35.47 v2(57.66,34.04) ; v2(51.82,37.08) v2(51.82,38.99)
FLEXSPI_CLK: length 18.6
  TOP w0.127: U1.L4 v1(55.82,52.65)
  BOTTOM w0.127: v1(55.82,52.65) 55.5,52.32 55.5,50.8 55.12,50.42 54.66,50.42 53.85,49.61 53.85,47.24 53.21,46.61 52.2,46.61 51.69,46.1 51.69,42.8 51.23,42.34 50.44,42.34 50.32,42.22 50.32,42.04 50.44,41.91 51.05,41.91 51.18,41.78 51.18,41.54 51.31,41.42 51.53,41.42 51.69,41.58 51.69,42.16 51.82,42.29 52,42.29 52.12,42.16 52.12,41.68 52.25,41.55 R361.1
FLEXSPI_CLK_B: length 20
  TOP w0.127: U1.P2 54.84,50.6 54.55,50.31 54.55,50.13 54.7,49.98 54.7,49.8 54.52,49.62 54.34,49.62 54.19,49.77 54.01,49.77 53.83,49.59 53.83,49.29 53.67,49.12 53.37,49.12 51.94,47.7 51.94,47.12 52.07,46.99 52.7,46.99 52.83,46.87 52.83,46.61 52.7,46.49 52.07,46.49 51.94,46.36 51.94,46.1 52.07,45.98 52.83,45.98 52.96,45.85 52.96,45.6 52.83,45.47 52.07,45.47 51.94,45.34 51.94,45.09 52.07,44.96 52.83,44.96 52.96,44.83 52.96,44.58 52.83,44.45 52.07,44.45 51.94,44.33 51.94,44.07 52.07,43.95 52.7,43.95 52.83,43.82 52.83,43.56 52.7,43.44 52.07,43.44 51.94,43.31 51.94,43.09 52.07,42.96 52.45,42.96 52.58,42.83 52.58,42.58 52.45,42.45 52.07,42.45 51.94,42.33 51.94,41.56 U19.B1
FLEXSPI_D0_A: length 19.2
  TOP w0.102: 55.24,41.68 54.84,41.27 54.46,41.27 54.36,41.17 54.36,40.51 54.61,40.26 54.99,40.26 55.24,40.01 v1(55.24,39.47)
  TOP w0.127: 55.24,41.68 55.24,43.31 53.72,44.83 53.72,45.29 54.99,46.56 54.99,47.37 54.65,47.71 54.65,48.76 55.5,49.61 55.5,51.02 U1.P3
  BOTTOM w0.127: R362.1 55.5,36.84 55.63,36.96 55.63,37.53 55.75,37.66 55.88,37.66 56.01,37.78 56.01,38.04 55.88,38.17 55.75,38.17 55.63,38.29 55.63,38.86 55.75,38.99 56.01,38.99 56.13,39.12 56.13,39.37 56.03,39.47 v1(55.24,39.47)
FLEXSPI_D0_B: length 20.5
  TOP w0.127: U19.D5 56.26,39.24 55.63,39.24 55.45,39.07 55.04,39.07 54.89,39.22 53.62,39.22 53.37,39.46 52.98,39.46 52.88,39.37 52.32,39.37 51.56,40.13 51.56,47.88 54.53,50.84 54.53,51.17 54.7,51.34 54.96,51.34 55.18,51.55 55.18,51.8 55.36,51.99 55.81,51.99 U1.M4
FLEXSPI_D1_A: length 18.5
  TOP w0.102: v1(55.75,40.26) 56.13,40.63 56.13,41.14
  TOP w0.127: U1.N4 55.83,51.35 55.83,49.45 55.6,49.22 55.6,48.92 55.83,48.69 55.83,48.46 55.46,48.09 55.46,45.43 55.89,45 55.89,43.9 56.74,43.05 57.51,43.05 57.78,42.77 57.78,42.42 57.23,41.87 57.23,41.41 57.11,41.28 56.27,41.28 56.13,41.14
  BOTTOM w0.127: R363.1 54.11,37.73 54.61,38.23 54.61,39.4 55.47,40.26 v1(55.75,40.26)
FLEXSPI_D1_B: length 20.4
  TOP w0.102: U1.M3 55.29,52.32 54.95,51.97 54.01,51.97 52.7,50.67 52.7,49.91
  TOP w0.127: 52.7,49.91 52.7,49.78 51.18,48.26 51.18,38.73 52.58,37.34 54.31,37.34 U19.E3
FLEXSPI_D2_A: length 18.5
  TOP w0.127: U1.P4 56.14,48.14 55.77,47.76 55.77,45.61 56.2,45.17 56.2,44.03 56.86,43.37 57.95,43.37 58.89,42.43 58.89,42.04 58.76,41.91 57.76,41.91 57.66,41.81 57.66,41.5 57.76,41.4 58.61,41.4 59.5,40.51 59.5,40.33 59.32,40.15 59.15,40.15 58.42,40.87 58.24,40.87 v1(57.63,40.26)
  BOTTOM w0.127: R364.1 R157.2 57.41,40.04 v1(57.63,40.26)
FLEXSPI_D2_B: length 20.3
  TOP w0.127: U19.E2 53.74,38.08 53.21,38.61 v1(53.21,39.04) ; U1.M5 v1(56.47,52)
  BOTTOM w0.102: v1(56.47,52) 56.57,52 57,51.56 57,50.81 57,50.81 57,49.91
  BOTTOM w0.127: v1(53.21,39.04) 53.65,39.04 53.78,39.17 53.78,39.35 53.58,39.56 53.58,39.73 53.76,39.91 53.94,39.91 54.14,39.71 54.32,39.71 54.74,40.13 54.74,41.91 54.64,42.01 54.64,44.4 55.02,44.78 55.02,45.72 55.14,45.85 56.26,45.85 56.39,45.97 56.39,46.17 56.28,46.28 55.48,46.28 55.37,46.39 55.37,46.61 55.5,46.74 56.28,46.74 56.39,46.85 56.39,48.39 57,49 57,49.91
FLEXSPI_D3_A: length 18.8
  TOP w0.127: v1(57.53,38.73) 57.53,39.62 57.66,39.75 57.87,39.75 58,39.62 58,39.24 58.13,39.12 58.38,39.12 58.51,39.24 58.51,39.62 58.63,39.75 59.64,39.75 59.92,40.03 59.92,41.86 58.1,43.68 56.99,43.68 56.5,44.16 56.5,45.35 56.07,45.78 56.07,47.56 56.54,48.03 56.54,50.77 U1.P5
  BOTTOM w0.127: R365.1 57.65,38.61 v1(57.53,38.73)
FLEXSPI_D3_B: length 20.4
  TOP w0.127: v1(52.96,38.23) 52.96,37.99 U19.E1 ; U1.L5 v1(56.47,52.65)
  BOTTOM w0.102: v1(56.47,52.65) 56.47,52.45 56.13,52.12 56.13,51.87 56.34,51.67 56.6,51.67 56.79,51.48 56.79,50.9 56.67,50.77 56.67,49.91
  BOTTOM w0.127: 56.67,49.91 56.67,49.26 55.88,48.47 55.88,48.12 55.77,48.01 54.98,48.01 54.86,47.9 54.86,47.68 55.02,47.53 55.77,47.53 55.88,47.41 55.88,47.22 55.75,47.09 54.98,47.09 54.86,46.98 54.86,46.1 54.71,45.95 54.71,44.91 54.33,44.53 54.33,43 53.72,42.39 53.72,40.39 53.59,40.26 53.41,40.26 53.34,40.33 53.16,40.33 52.98,40.15 52.98,39.97 53.05,39.9 53.05,39.72 52.7,39.37 52.7,38.48 v1(52.96,38.23)
FLEXSPI_DQS: length 18.5
  TOP w0.127: v1(54.1,42.29) 54.1,41.53 53.98,41.4 53.21,41.4 53.08,41.54 52.44,41.54 52.31,41.67 52.31,41.92 52.44,42.05 53.2,42.05 53.34,42.18 53.34,45.34 54.61,46.61 54.61,47.16 54.23,47.55 54.23,48.08 54.1,48.21 53.84,48.21 53.72,48.08 53.72,47.88 53.59,47.75 53.01,47.75 52.88,47.88 52.88,48.06 53.54,48.72 54.18,48.72 55.17,49.71 55.17,51.14 55.49,51.47 U1.N3
  BOTTOM w0.127: v1(54.1,42.29) 54.1,41.7 R366.1
FLEXSPI_SS0: length 19.7
  TOP w0.127: v2(53.85,46.53) 53.85,46.61 v2(53.21,47.24) ; U1.L3 v1(55.17,52.65)
  BOTTOM w0.102: 53.47,49.61 54.66,50.8 54.99,50.8 55.17,50.98 v1(55.17,52.65)
  BOTTOM w0.127: R427.1 53.85,46.49 v2(53.85,46.53) ; R153.1 50.29,40.89 R356.1 49.91,41.28 49.91,42.55 50.44,43.08 50.62,43.08 50.89,42.81 51.07,42.81 51.25,42.99 51.25,43.17 50.98,43.44 50.98,43.62 51.18,43.81 51.18,44.01 51.05,44.14 50.8,44.14 50.67,44.26 50.67,44.52 50.8,44.65 51.05,44.65 51.18,44.77 51.18,46.23 51.94,46.99 52.96,46.99 v2(53.21,47.24) 53.47,47.5 53.47,49.61
GPIO_AD_B0_00: length 58.1
  TOP w0.127: R341.1 90.42,28.32 91.31,29.21 93.54,29.21 93.85,28.9 95.06,28.9 96.77,30.61 96.77,32.51 92.96,36.32 92.96,43.59 92.1,44.45 88.77,44.45 84.44,48.78 83.17,48.78 82.85,49.11 74.85,49.11 R57.2 72.52,50.8 71.08,52.24 62.95,52.24 62.87,52.32 U1.M14
GPIO_AD_B0_01: length 95
  TOP w0.127: U1.H10 v1(60.37,54.6) ; v2(90.04,46.48) 90.55,46.48 93.34,43.69 93.34,36.83 97.28,32.89 97.28,29.84 95.12,27.69 v2(95.12,18.29) 95.12,11.94 92.58,9.4 R71.2 ; Q15.2 v2(83.69,17.95)
  BOTTOM w0.102: v1(60.37,54.6) 60.69,54.92 62.3,54.92 62.61,54.61 R55.2
  BOTTOM w0.127: v2(83.69,17.95) 84.03,18.29 v2(95.12,18.29) ; v2(90.04,46.48) 90.04,49.71 81.84,57.91 66.8,57.91 64.26,55.37 63.75,55.37 R55.2
GPIO_AD_B0_02: length 234.8
  TOP w0.127: v1(61.02,52) U1.M11 ; v2(85.6,49.66) 86.23,50.29 103.2,50.29 110.19,57.28 114.43,57.28 v2(114.94,57.78) ; v2(34.8,72.01) 34.29,72.52 34.29,73.11 28.79,78.61 25.28,78.61 J24.2 ; v2(83.69,16.76) R329.1 ; v2(91.44,28.32) 92.58,27.18 v2(92.58,17.65)
  BOTTOM w0.102: 64.14,51.03 62.97,51.03 62.87,50.93 62.26,50.93 61.19,52 v1(61.02,52)
  BOTTOM w0.127: J24.2 26.07,83.36 53.92,83.36 59.01,88.45 87.85,88.45 111.02,65.28 113.41,65.28 114.94,63.75 v2(114.94,57.78) ; J8.B2 35.01,71.8 v2(34.8,72.01) ; 64.14,51.03 67.28,51.03 68,51.74 75.49,51.74 77.67,53.92 79.81,53.92 81.53,52.2 82.37,52.2 83.1,51.47 83.1,50.76 84.2,49.66 v2(85.6,49.66) 85.72,49.53 85.72,44.7 87.88,42.55 87.88,31.88 v2(91.44,28.32) ; v2(92.58,17.65) 84.58,17.65 v2(83.69,16.76)
GPIO_AD_B0_03: length 248.7
  TOP w0.127: v2(118.11,23.24) 118.11,30.73 118.53,31.15 118.53,31.97 v2(118.11,32.38) ; v2(94.49,17.27) v2(94.49,26.29) ; U1.G11 v1(61.02,55.89) ; R334.1 v2(87.76,16.76)
  BOTTOM w0.102: 65.15,58.04 63.37,56.26 61.39,56.26 v1(61.02,55.89)
  BOTTOM w0.127: v2(94.49,17.27) 93.5,16.28 88.24,16.28 v2(87.76,16.76) ; 65.15,58.04 66.29,59.18 81.87,59.18 91.33,49.72 91.33,43.21 92.5,42.04 93.34,42.04 95.25,40.13 95.25,36.83 94.11,35.69 94.11,26.67 v2(94.49,26.29) 97.16,23.62 117.73,23.62 v2(118.11,23.24) ; v2(118.11,32.38) 118.11,33.78 118.62,34.29 118.62,49.71 114.41,53.91 114.41,63.51 113.67,64.26 111.6,64.26 87.72,88.14 59.14,88.14 54.05,83.06 28.3,83.06 J24.1
GPIO_AD_B0_04: length 93.1
  TOP w0.127: v2(88.01,53.98) 88.43,54.39 103.96,54.39 107.28,57.71 107.28,73.44 106.64,74.08 106.64,78.49 104.11,81.03 92.71,81.03 91.95,81.78 R259.2 89.25,82.32 SW7.4 ; U1.F11 v1(61.02,56.54)
  BOTTOM w0.127: v2(88.01,53.98) 87.5,53.98 81.92,59.56 66.17,59.56 63.15,56.54 v1(61.02,56.54)
GPIO_AD_B0_11: length 175
  TOP w0.127: v2(41.91,77.47) 36.7,77.47 34.29,75.06 v2(34.29,74.3) 38.73,74.3 39.24,74.8 51.56,74.8 56.9,69.47 65.15,69.47 67.56,71.88 R264.2 v2(68.33,75.56) R261.2 ; J22.3 42.6,83.24 42.8,83.44 42.8,86.99 42.42,87.37 R178.2 42.18,88.01 43.43,89.27 43.43,94.02 J21.3 ; v2(77.6,77.09) 78.11,77.6 99.69,77.6 103.58,73.71 103.58,58.85 102.43,57.7 87.06,57.7 85.72,59.03 v2(85.72,59.69) ; U1.G10 v1(60.37,55.89)
  BOTTOM w0.102: v1(60.37,55.89) 60.7,56.22 60.7,56.71 60.86,56.87 62.97,56.87 64.64,58.55
  BOTTOM w0.127: J22.3 42.6,78.16 v2(41.91,77.47) ; 64.64,58.55 66.04,59.94 85.47,59.94 v2(85.72,59.69) ; J8.B3 34.51,71.41 34.29,71.63 v2(34.29,74.3) ; v2(77.6,77.09) 76.83,76.33 69.09,76.33 v2(68.33,75.56)
GPIO_AD_B1_00: length 370.3
  TOP w0.127: v2(125.09,21.59) 125.35,21.84 125.48,21.84 125.88,22.25 U13.17 ; U1.J11 v1(61.02,53.95) ; R277.2 v2(75.18,4.06) ; v2(135.64,15.75) 138.18,15.75 139.44,14.48 R234.2 139.44,12.95 138.56,12.06 v2(138.56,10.67) 138.56,10.03 137.67,9.14 137.16,9.14 136.47,8.45 J35.20 ; v2(33.78,72.77) 33.53,72.52 33.53,71.12 26.67,64.26 26.67,56.52 27.3,55.88 27.3,46.86 28.71,45.45 30.37,45.45 v2(30.86,44.96) ; R272.2 R270.2 v2(54.99,74.3) ; v2(81.92,56.13) 83.82,56.13 84.32,55.64 103.28,55.64 105.79,58.15 v2(105.79,62.36)
  BOTTOM w0.102: 65.15,53.4 62.67,53.4 62.45,53.62 61.34,53.62 v1(61.02,53.95)
  BOTTOM w0.127: v2(30.86,44.96) 31.68,44.14 31.68,42.08 32.66,41.1 37.49,41.1 44.17,34.42 45.97,34.42 46.61,33.78 46.61,33.41 J23.6 ; v2(75.18,4.06) 78.11,6.99 87.13,6.99 88.52,8.38 88.52,11.94 90.68,14.1 99.95,14.1 101.47,15.62 118.11,15.62 123.83,9.91 133.86,9.91 134.62,10.67 v2(138.56,10.67) ; 65.15,53.4 65.72,53.4 66.35,54.03 72.69,54.03 75.18,56.52 81.53,56.52 v2(81.92,56.13) ; v2(135.64,15.75) 133.1,15.75 132.48,16.37 125.87,16.37 124.84,17.4 124.84,20.7 125.09,20.95 v2(125.09,21.59) 125.35,21.84 125.35,22.64 116.33,31.65 116.33,33.53 117.63,34.82 117.63,49.33 105.79,61.16 v2(105.79,62.36) 105.28,62.87 105.28,67.69 86.66,86.32 70.31,86.32 67.82,83.82 67.82,76.45 66.93,75.56 59.82,75.56 58.04,73.79 58.04,71.75 57.78,71.5 56.9,71.5 54.99,73.41 v2(54.99,74.3) 54.99,75.06 54.23,75.82 35.05,75.82 33.53,74.3 33.53,73.03 v2(33.78,72.77) 33.53,72.52 33.53,71.88 34.01,71.4 J8.B4
GPIO_AD_B1_01: length 379.4
  TOP w0.127: v2(82.04,54.61) 83.69,54.61 84.42,55.33 103.41,55.33 106.3,58.22 106.3,64.02 v2(105.8,64.52) ; U13.18 126.38,21.99 126.24,21.84 v2(125.98,21.59) ; v2(57.53,72.01) 57.53,71.37 58.03,70.87 R271.2 R273.2 ; U1.K11 v1(61.02,53.3) ; v2(29.97,44.96) 29.84,45.09 28.45,45.09 26.92,46.61 26.92,55.5 26.34,56.08 26.34,64.47 33.15,71.28 33.15,72.52 v2(32.89,72.77) ; J35.22 137.47,8.43 139.06,10.03 v2(139.06,11.3) 140.96,13.2 R232.2 140.96,14.99 139.57,16.38 v2(134.75,16.38) ; R276.2 v2(72.4,4.06)
  BOTTOM w0.102: 65.15,52.79 62,52.79 61.83,52.97 61.46,52.97 61.13,53.3 v1(61.02,53.3)
  BOTTOM w0.127: v2(134.75,16.38) 133.1,16.38 132.72,16.76 126.24,16.76 125.22,17.78 125.22,20.19 125.98,20.95 v2(125.98,21.59) 125.73,21.84 125.73,22.73 116.69,31.77 116.69,33.38 117.93,34.62 117.93,49.45 106.3,61.09 106.3,64.02 v2(105.8,64.52) 105.8,67.68 86.86,86.62 70.07,86.62 67.43,83.98 67.43,76.7 66.8,76.07 59.82,76.07 57.53,73.79 v2(57.53,72.01) 56.9,72.01 55.69,73.22 55.69,74.99 54.48,76.2 34.89,76.2 33.15,74.45 33.15,73.03 v2(32.89,72.77) 33.15,72.52 33.15,71.63 33.51,71.27 J8.B5 ; v2(82.04,54.61) 82.04,54.79 80.98,55.85 75.79,55.85 73.33,53.39 66.95,53.39 66.36,52.79 65.15,52.79 ; v2(72.4,4.06) 74.16,4.06 77.6,7.49 86.92,7.49 88.02,8.59 88.02,12.15 90.35,14.48 99.79,14.48 101.32,16 118.27,16 123.98,10.29 133.7,10.29 134.72,11.3 v2(139.06,11.3) ; J23.5 46.23,33.42 46.23,33.66 45.85,34.04 44.02,34.04 37.26,40.79 32.49,40.79 30.99,42.29 30.99,43.94 v2(29.97,44.96)
GPIO_AD_B1_03: length 209.6
  TOP w0.127: U1.M12 61.68,51.99 62.13,51.99 62.32,51.79 v1(62.32,51.35) ; v2(83.57,51.18) 84.2,51.18 84.29,51.27 103.32,51.27 111.32,59.27 115.15,59.27 J15.1 113.79,63.5 v2(113.67,63.5) ; v2(28.7,77.98) 26.01,75.29 26.01,47.02 28.57,44.45 32.26,44.45 33.15,43.56 33.15,42.8 32.26,41.91 D6.C
  BOTTOM w0.102: 64.14,51.4 62.37,51.4 v1(62.32,51.35)
  BOTTOM w0.127: v2(28.7,77.98) 28.7,79.4 J22.8 31.98,82.68 54.21,82.68 59.37,87.84 87.6,87.84 111.93,63.5 v2(113.67,63.5) ; 64.14,51.4 67.14,51.4 67.82,52.07 75.18,52.07 77.34,54.23 79.93,54.23 81.58,52.58 82.42,52.58 83.57,51.44 v2(83.57,51.18)
GPIO_AD_B1_04: length 100.7
  TOP w0.127: U1.L12 v1(61.67,52.65) ; R217.2 v2(128.91,13.34)
  BOTTOM w0.102: 65.15,52.48 61.84,52.48 v1(61.67,52.65)
  BOTTOM w0.127: v2(128.91,13.34) 122.95,13.34 114.69,21.59 96.59,21.59 92.58,25.6 92.58,30.99 88.91,34.66 88.91,42.79 87.63,44.07 R290.2 87.12,46.49 87,46.62 87,48.26 87.5,48.77 87.5,50.53 84.12,53.91 81.54,53.91 80.21,55.24 75.95,55.24 73.79,53.09 67.08,53.09 66.47,52.48 65.15,52.48
GPIO_AD_B1_05: length 104.8
  TOP w0.127: U1.K12 v1(61.67,53.3) ; R218.2 v2(132.72,13.34)
  BOTTOM w0.102: v1(61.67,53.3) 61.86,53.3 62.06,53.1 65.15,53.1
  BOTTOM w0.127: v2(132.72,13.34) 132.21,13.84 122.87,13.84 114.75,21.97 97.03,21.97 93.09,25.91 93.09,31.5 89.41,35.18 89.41,42.8 88.14,44.07 88.14,46.99 88.39,47.24 R291.2 88.77,47.75 88.52,48.01 88.52,49.94 84.12,54.34 83,54.34 81.18,56.16 75.46,56.16 73.03,53.72 66.85,53.72 66.23,53.1 65.15,53.1
GPIO_AD_B1_06: length 122.5
  TOP w0.127: R220.2 v2(137.79,12.19) ; v2(117.64,22.35) 117.64,30.97 v2(118.06,31.39) ; U1.J12 v1(61.02,54.59)
  BOTTOM w0.102: 62.44,53.95 62.11,54.27 61.34,54.27 v1(61.02,54.59)
  BOTTOM w0.127: 62.44,53.95 62.67,53.71 65.52,53.71 66.14,54.33 72.24,54.33 74.8,56.9 81.92,56.9 82.55,56.26 82.55,55.24 83.14,54.65 84.24,54.65 88.9,49.99 88.9,48.13 89.53,47.5 89.53,44.83 89.86,44.51 89.86,35.76 93.61,32 93.61,26.4 97.16,22.86 117.13,22.86 v2(117.64,22.35) 117.64,19.51 123,14.15 136.47,14.15 137.79,12.83 v2(137.79,12.19) ; R289.2 117.35,32.1 v2(118.06,31.39)
GPIO_AD_B1_07: length 106.8
  TOP w0.127: R221.2 v2(135.25,12.06) ; U1.K10 v1(60.37,53.3)
  BOTTOM w0.102: 64.47,51.77 61.71,51.77 61.15,52.32 60.89,52.32 60.69,52.51 60.69,52.97 v1(60.37,53.3)
  BOTTOM w0.127: v2(135.25,12.06) 134.62,12.7 128.4,12.7 128.14,12.95 122.85,12.95 114.72,21.08 96.27,21.08 92.08,25.27 92.08,30.61 88.39,34.29 88.39,42.55 86.24,44.7 R288.2 85.98,50.04 85.85,50.16 85.34,50.16 82.55,52.96 81.63,52.96 80.06,54.53 76.76,54.53 74.63,52.4 67.64,52.4 67.01,51.77 64.47,51.77
GPIO_AD_B1_09: length 82.7
  TOP w0.127: R102.1 120.31,26.68 118.87,25.25 v2(118.87,24.89) ; v2(92.46,43.43) 91.95,43.94 88.85,43.94 84.32,48.48 82.97,48.48 82.64,48.8 73.93,48.8 70.8,51.93 62.83,51.93 62.76,52 62.5,52 62.18,52.32 U1.M13
  BOTTOM w0.127: R223.2 119.01,24.76 v2(118.87,24.89) 97.45,24.89 95.12,27.22 95.12,33.78 96.01,34.67 96.01,40.89 93.47,43.43 v2(92.46,43.43)
GPIO_AD_B1_10: length 97.5
  TOP w0.127: U1.L13 62.31,52.65 62.86,52.65 62.97,52.54 74.46,52.54 76.52,50.48 78.36,50.48 78.61,50.23 80.71,50.23 v2(81.53,51.05) ; R224.2 v2(130.18,12.06)
  BOTTOM w0.127: v2(81.53,51.05) R285.2 81.53,43.94 86.87,38.61 86.87,31.11 90.17,27.81 90.17,24.51 94.61,20.07 114.87,20.07 123.38,11.56 129.67,11.56 v2(130.18,12.06)
GPIO_AD_B1_11: length 94.5
  TOP w0.127: R225.2 v2(127.64,12.06) ; U1.J13 62.33,53.94 62.78,53.94 63.26,53.45 74.84,53.45 76.86,51.44 78.99,51.44 v2(79.12,51.31)
  BOTTOM w0.127: v2(79.12,51.31) 79.12,51.31 R286.2 80.14,51.31 80.52,51.69 82.42,51.69 82.79,51.32 82.79,50.18 85.34,47.62 85.34,44.45 87.38,42.42 87.38,31.5 90.93,27.94 90.93,25.65 96.01,20.57 114.8,20.57 122.8,12.57 127.13,12.57 v2(127.64,12.06)
GPIO_AD_B1_12: length 90.8
  TOP w0.127: v2(89.53,48.39) 93.73,44.2 93.73,37.21 99.57,31.37 99.57,22.45 101.7,20.32 119.76,20.32 v2(120.4,19.68) 121.55,19.68 R100.1 ; U1.H12 v1(61.67,54.6)
  BOTTOM w0.102: v1(61.67,54.6) 62.24,54.6 62.87,53.98 65.02,53.98 65.15,54.1
  BOTTOM w0.127: 65.15,54.1 66.1,55.05 66.1,56.58 67.06,57.53 81.79,57.53 89.53,49.79 v2(89.53,48.39) ; R226.2 120.66,19.68 v2(120.4,19.68)
GPIO_AD_B1_13: length 89.8
  TOP w0.127: R101.1 v2(121.44,22.88) 120.65,22.1 119.89,22.1 119.13,21.34 102.11,21.34 100.46,22.99 100.46,32.26 v2(94.74,37.97) ; U1.H11 v1(61.02,55.24)
  BOTTOM w0.127: v2(94.74,37.97) 93.47,39.24 93.47,39.88 90.55,42.8 90.55,49.63 81.82,58.36 66.75,58.36 64.01,55.63 62.05,55.63 61.67,55.24 v1(61.02,55.24) ; R227.2 122.18,22.14 v2(121.44,22.88)
GPIO_AD_B1_14: length 91.8
  TOP w0.127: v2(94.74,39.88) 101.22,33.4 101.22,22.99 102.36,21.84 118.87,21.84 120.52,23.5 v2(120.52,24.13) 120.52,24.77 121.17,25.41 R99.1 ; U1.G12 v1(61.67,55.89)
  BOTTOM w0.127: v1(61.67,55.89) 63.64,55.89 66.55,58.8 81.82,58.8 90.94,49.67 90.94,43.04 92.71,41.27 93.34,41.27 v2(94.74,39.88) ; R228.2 121.93,23.37 121.16,23.37 120.52,24 v2(120.52,24.13)
GPIO_AD_B1_15: length 87.3
  TOP w0.127: v2(91.57,52.45) 91.38,52.26 80.25,52.26 79.77,51.78 77,51.78 75.02,53.76 63.35,53.76 62.84,54.27 U1.J14 ; R98.1 v2(121.42,24.14)
  BOTTOM w0.127: v2(91.57,52.45) 92.33,52.45 93.85,50.93 93.85,43.74 96.39,41.2 96.39,33.27 95.63,32.51 95.63,27.43 97.64,25.43 119.02,25.43 119.51,25.91 120.02,25.91 120.4,25.53 120.4,25.17 v2(121.42,24.14) R98.1
GPIO_B0_04: length 34.8
  TOP w0.127: v2(83.69,69.22) 83.31,68.83 83.31,68.57 R247.2 82.99,68.25 81.84,68.25 81.15,67.56 79.38,67.56 76.19,64.38 62.65,64.38 59.25,60.97 59.25,60.65 59.08,60.48 59.08,58.5 U1.C8
  BOTTOM w0.127: R325.2 83.15,72.73 J8.A24 83.15,69.76 v2(83.69,69.22)
GPIO_B0_05: length 58.3
  TOP w0.127: SW5.1 v2(68.93,82.42) ; U1.B8 58.75,58.98 58.42,59.31 58.42,61.31 62.31,65.2 75.62,65.2 79.5,69.09 79.5,69.98 79.88,70.36 80.96,70.36 81.15,70.17 R248.2 82.42,69.72 v2(82.8,69.34)
  BOTTOM w0.127: v2(82.8,69.34) 82.65,69.5 J8.A25 82.65,77.47 79.73,80.39 77.22,80.39 73.79,83.82 70.33,83.82 v2(68.93,82.42)
GPIO_B0_06: length 52.9
  TOP w0.127: U1.A8 58.75,60.78 58.84,60.87 58.84,61.14 62.48,64.79 75.89,64.79 78.97,67.87 80.95,67.87 81.15,68.07 R249.2 81.15,68.83 81.41,69.09 v2(81.79,69.09) ; SW5.2 v2(70.2,82.42)
  BOTTOM w0.127: v2(81.79,69.09) 82.02,69.09 82.15,69.22 J8.A26 82.15,77.26 79.52,79.89 76.83,79.89 73.41,83.31 71.09,83.31 v2(70.2,82.42)
GPIO_B0_07: length 50
  TOP w0.127: R250.2 v2(80.52,67.06) 79.5,67.06 76.44,64 62.81,64 59.63,60.81 59.63,60.52 59.4,60.28 U1.A9 ; SW5.3 v2(71.47,82.33)
  BOTTOM w0.127: v2(71.47,82.33) 71.95,82.8 73.15,82.8 76.83,79.12 79.38,79.12 81.65,76.85 J8.A27 81.65,69.84 80.52,68.71 v2(80.52,67.06)
GPIO_B0_08: length 48.8
  TOP w0.127: R251.2 80.77,65.91 v2(80.52,66.17) 77.9,63.55 62.99,63.55 60.07,60.63 60.07,60.47 59.71,60.11 59.71,59.14 U1.B9 ; SW5.4 v2(72.74,82.26)
  BOTTOM w0.127: v2(80.52,66.17) 80.04,66.65 80.04,68.73 81.15,69.85 J8.A28 81.15,76.46 79.12,78.49 76.52,78.49 v2(72.74,82.26)
GPIO_B0_09: length 59.4
  TOP w0.127: v2(87.88,68.33) R252.2 84.96,67.56 84.71,67.31 84.71,66.17 v2(84.45,65.91) ; U1.C9 v1(59.72,58.49) ; SW6.1 v2(77.18,84.84)
  BOTTOM w0.102: 60.7,60.58 59.72,59.6 v1(59.72,58.49)
  BOTTOM w0.127: v2(77.18,84.84) 77.95,84.07 81.79,84.07 84.71,81.15 85.6,81.15 87.65,79.1 J8.A15 87.65,68.56 v2(87.88,68.33) ; v2(84.45,65.91) 81.14,62.59 62.71,62.59 60.7,60.58
GPIO_B0_10: length 50
  TOP w0.127: U1.D9 v1(59.72,57.84) ; v2(87.15,69.22) 87,69.22 86.35,68.57 R253.2 86.35,68.08 86.14,67.87 84.68,67.87 84.33,67.51 84.33,66.67 v2(83.57,65.91) ; SW7.1 v2(85.44,80.52)
  BOTTOM w0.102: 59.76,60.07 59.4,59.71 59.4,58.33 59.72,58.01 v1(59.72,57.84)
  BOTTOM w0.127: 59.76,60.07 62.59,62.9 80.55,62.9 v2(83.57,65.91) ; v2(85.44,80.52) 87.15,78.81 J8.A16 v2(87.15,69.22)
GPIO_B0_11: length 54.7
  TOP w0.127: U1.A10 60.05,60.05 60.52,60.52 60.52,60.64 63.12,63.25 78.36,63.25 80.1,64.99 84.29,64.99 85.09,65.79 87,65.79 87.13,65.91 R254.2 v2(87.13,67.06) ; SW6.2 v2(78.45,82.42)
  BOTTOM w0.127: v2(87.13,67.06) 86.65,67.53 J8.A17 86.65,78.32 81.53,83.44 79.47,83.44 v2(78.45,82.42)
GPIO_B0_12: length 53.1
  TOP w0.127: U1.C10 v1(60.37,58.49) ; R255.2 86.1,69.27 v2(86.15,69.22) ; SW6.3 v2(79.72,82.42)
  BOTTOM w0.102: v1(60.37,58.49) 60.37,58.69 60.83,59.15 60.83,59.84
  BOTTOM w0.127: 60.83,59.84 62.96,61.97 83.05,61.97 85.72,64.64 85.72,67.21 86.15,67.64 v2(86.15,69.22) J8.A18 86.15,78.06 81.28,82.93 80.23,82.93 v2(79.72,82.42)
GPIO_B0_13: length 53.8
  TOP w0.127: SW7.2 86.71,80.87 85.72,79.88 v2(83.31,79.88) 82.43,79.88 R428.1 ; U1.D10 v1(60.37,57.84) ; R256.2 85.35,66.92 v2(85.22,67.06)
  BOTTOM w0.102: 60.71,60.16 60.05,59.49 60.05,58.17 v1(60.37,57.84)
  BOTTOM w0.127: v2(83.31,79.88) 85.65,77.54 J8.A19 85.65,68 85.22,67.56 v2(85.22,67.06) 85.22,65.28 82.22,62.28 62.83,62.28 60.71,60.16
GPIO_B0_14: length 51.6
  TOP w0.127: SW6.4 v2(80.99,82.42) ; R257.2 v2(83.06,67.74) ; U1.E10 v1(60.37,57.19)
  BOTTOM w0.102: 59.84,60.58 59.19,59.94 59.19,58.21 59.39,58 59.39,57.57 59.56,57.4 60.16,57.4 v1(60.37,57.19)
  BOTTOM w0.127: 59.84,60.58 62.46,63.2 80.22,63.2 82.04,65.02 82.04,66.04 R257.2 v2(83.06,67.74) 83.77,68.45 84.38,68.45 85.15,69.22 J8.A20 85.15,77.03 80.99,81.18 v2(80.99,82.42)
GPIO_B0_15: length 42.6
  TOP w0.127: v2(91.31,68.45) 91.06,68.71 91.06,69.72 R258.2 R324.2 ; U1.E11 v1(61.02,57.19)
  BOTTOM w0.102: 63.37,58.93 61.59,58.93 61.35,58.68 61.35,58.36 61.35,58.36 61.35,57.52 v1(61.02,57.19)
  BOTTOM w0.127: 63.37,58.93 65.46,61.01 84.38,61.01 85.9,62.53 88.19,62.53 90.93,65.28 90.93,67.82 91.31,68.2 v2(91.31,68.45) 91.15,68.62 J8.A8
GPIO_SD_B0_00: length 53.7
  TOP w0.127: U1.J4 v1(55.82,53.95) ; v2(15.11,52.98) 14.58,52.45 13.84,52.45 13.31,52.98 J39.3
  BOTTOM w0.102: 52.32,52.83 53.24,53.75 54.46,53.75 54.58,53.62 55.5,53.62 v1(55.82,53.95)
  BOTTOM w0.127: R280.2 v2(15.11,52.98) 15.11,52.43 14.99,52.3 14.73,52.3 14.61,52.18 14.61,51.92 14.73,51.79 15.52,51.79 20.57,46.74 32,46.74 32.38,46.35 41.02,46.35 42.68,48.02 45.83,48.02 49.12,51.31 50.04,51.31 50.41,50.93 R59.2 50.8,50.8 51.69,51.69 51.69,51.89 52.2,52.4 52.2,52.71 52.32,52.83
GPIO_SD_B0_01_B: length 34.5
  TOP w0.127: J39.5 16.96,55.18 v2(17.02,55.12)
  BOTTOM w0.127: R282.2 38.1,48.38 C245.1 37.08,48.51 36.59,48.51 36.46,48.39 36.46,48.26 36.33,48.13 36.08,48.13 35.95,48.26 35.95,48.39 35.83,48.51 35.57,48.51 35.45,48.39 35.45,48.26 35.32,48.13 35.06,48.13 34.94,48.26 34.94,48.39 34.81,48.51 34.56,48.51 34.43,48.39 34.43,48.26 34.3,48.13 34.05,48.13 33.92,48.26 33.92,48.39 33.79,48.51 33.54,48.51 33.41,48.39 33.41,48.26 33.29,48.13 33.03,48.13 32.91,48.26 32.91,48.39 32.78,48.51 21.08,48.51 20.88,48.72 20.88,48.9 21.08,49.1 21.08,49.28 20.9,49.46 20.72,49.46 20.52,49.26 20.34,49.26 20.16,49.44 20.16,49.62 20.42,49.88 20.42,50.06 20.24,50.24 20.06,50.24 19.8,49.98 19.62,49.98 17.02,52.58 v2(17.02,55.12) R281.2
GPIO_SD_B0_02: length 55
  TOP w0.127: U1.J1 53.82,54.27 53.47,53.92 50.88,53.92 50.4,53.45 v2(50.4,52.32) 50.4,52.31 R60.2 ; v2(16.26,57.28) 16.13,57.15 14.73,57.15 14.5,57.38 J39.7
  BOTTOM w0.127: R279.2 16.38,57.4 v2(16.26,57.28) 16.26,54.74 16.51,54.48 16.51,53.85 16.26,53.59 16.26,52.58 20.7,48.13 32.13,48.13 33.15,47.12 40.77,47.12 42.29,48.64 45.59,48.64 48.89,51.94 50.02,51.94 v2(50.4,52.32)
GPIO_SD_B0_03: length 53.7
  TOP w0.127: v2(15.11,58.48) J39.8 ; U1.K1 53.89,53.31 52.42,53.31 v2(51.66,52.55)
  BOTTOM w0.127: R278.2 v2(15.11,58.48) 15.75,57.84 15.75,52.32 20.95,47.12 32.38,47.12 32.77,46.74 40.89,46.74 42.48,48.32 45.7,48.32 48.99,51.61 50.72,51.61 v2(51.66,52.55)
HP_JD: length 33.9
  TOP w0.254: U13.7 126.38,28.12 v2(126.33,28.17) ; v2(140.06,25.17) 140.06,24.47 138.58,22.99 136.02,22.99 135.43,22.4 135.43,20.27 133.24,18.07 R275.2
  TOP w0.381: TVS3.2 R94.2 v2(140.06,25.17)
  TOP w0.508: J12.5 TVS3.2
  BOTTOM w0.305: v2(140.06,25.17) 140.06,25.29 138.94,26.42 137.11,26.42 135.35,28.17 v2(126.33,28.17)
HP_L: length 2.4
  TOP w0.279: U13.31 131.21,26.16 131.95,26.9 C230.1
HP_MIC1N: length 3.4
  TOP w0.254: U13.4 127.89,28.19 128.78,29.08 C121.2
  TOP w0.305: C123.1 C121.2
HP_MIC1P: length 4.1
  TOP w0.254: C127.1 130.56,29.08 130.18,28.7 129.54,28.7 128.91,28.07 128.91,27.32 U13.2
  TOP w0.305: C125.1 C127.1
HP_R: length 2.1
  TOP w0.279: C231.1 131.58,25.15 U13.29
JTAG_DACK: length 9
  TOP w0.127: R182.1 23.13,88.64 23.13,94.01 J21.19
JTAG_DE: length 9
  TOP w0.127: R174.2 25.67,88.64 25.67,94.01 J21.17
